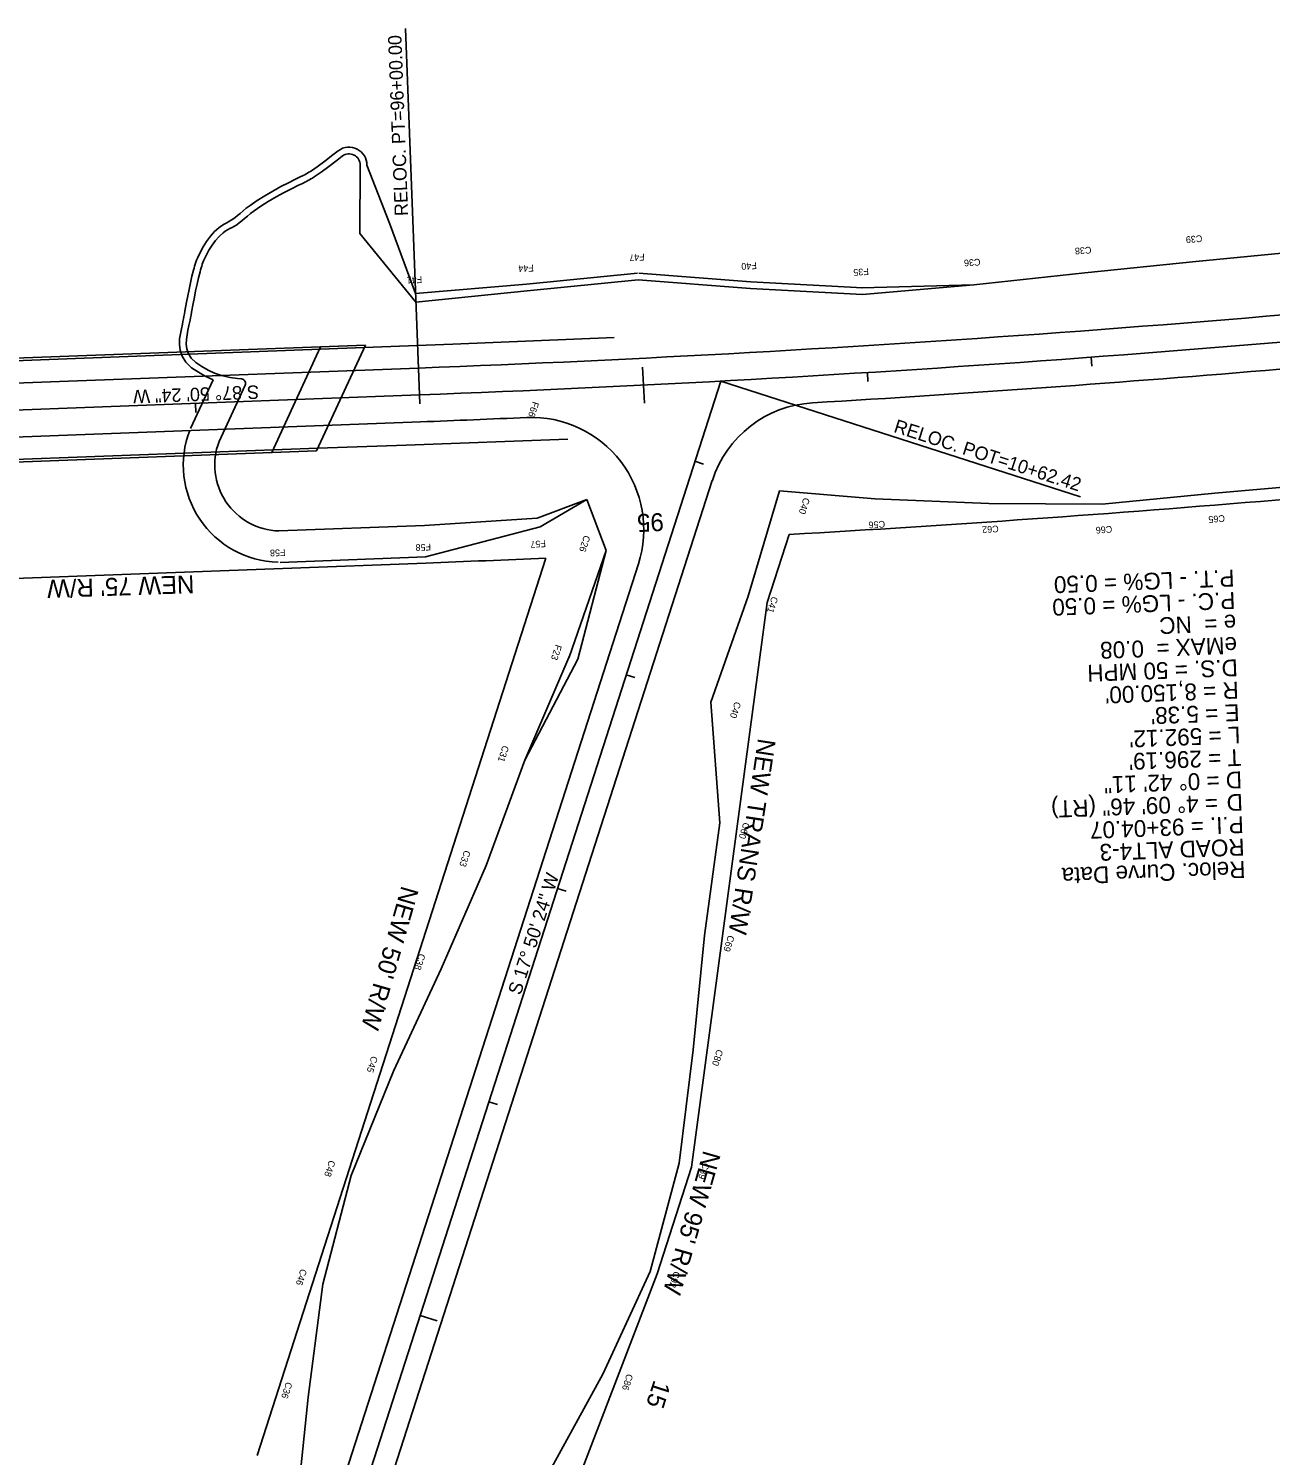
# Model space of a CAD drawing. Extents: x 1475170 to 1480100, y 1103245 to 1119475.
# Drawn here: x 1477070 to 1477624, y 1110840 to 1111476 of the extents above; entities that cross this region are included whole.
import ezdxf

# ---------------------------------------------------------------- set-up
doc = ezdxf.new("R2010")
doc.units = 0
for name, color, linetype in [('RD_HC_CL_Rel', 7, 'Continuous'), ('RD_HC_Data_Rel', 7, 'Continuous'), ('RD_HC_Data_Tic_Rel', 7, 'Continuous'), ('RD_HC_TX_Rel_Sta50', 7, 'Continuous'), ('RD_PD_Bridge', 7, 'Continuous'), ('RD_PD_CstnLmt', 7, 'Continuous'), ('RD_PD_CstnLmt_TX', 7, 'Continuous'), ('RD_PD_DR_ErosCtrl', 7, 'Continuous'), ('RD_PD_Final_TrvlWay', 7, 'Continuous'), ('RD_PD_GR', 7, 'Continuous'), ('RD_PD_RW', 7, 'Continuous'), ('RD_PD_RW_TX', 7, 'Continuous')]:
    doc.layers.add(name, color=color, linetype=linetype)

msp = doc.modelspace()

# ---------------------------------------------------------------- linework, layer by layer
at = {"layer": 'RD_HC_CL_Rel'}
for p, q in [((1477378.79, 1111318.79), (1477219.71, 1110824.5)), ((1477244.45, 1111312.61), (1477044.6, 1111305.07))]:
    msp.add_line(p, q, dxfattribs=at)
msp.add_arc((1476937.28, 1119456.82), 8150, 272.160003, 276.322689, dxfattribs=at)
at = {"layer": 'RD_HC_Data_Rel'}
for p, q in [((1477244.45, 1111312.61), (1477238.29, 1111475.96)), ((1477378.79, 1111318.79), (1477539.19, 1111267.17))]:
    msp.add_line(p, q, dxfattribs=at)
at = {"layer": 'RD_HC_Data_Tic_Rel'}
for p, q in [((1477344.36, 1111316.99), (1477343.96, 1111324.98)), ((1477543.97, 1111329.43), (1477544.26, 1111325.45)), ((1477444.2, 1111322.6), (1477444.45, 1111318.61)), ((1477244.45, 1111312.61), (1477244.61, 1111308.62)), ((1477344.36, 1111316.99), (1477344.76, 1111309)), ((1477144.53, 1111308.84), (1477144.68, 1111304.85)), ((1477367.28, 1111283.02), (1477371.09, 1111281.79)), ((1477336.64, 1111187.83), (1477340.45, 1111186.6)), ((1477306.01, 1111092.63), (1477309.82, 1111091.41)), ((1477275.37, 1110997.44), (1477279.18, 1110996.22)), ((1477244.74, 1110902.25), (1477252.35, 1110899.8))]:
    msp.add_line(p, q, dxfattribs=at)
at = {"layer": 'RD_PD_Bridge'}
for p, q in [((1477219.85, 1111333.7), (1476890.09, 1111321.26)), ((1477220.38, 1111334.85), (1476890.62, 1111322.41)), ((1477200.4, 1111334.09), (1477178.59, 1111286.99)), ((1477220.38, 1111334.85), (1477198.58, 1111287.74)), ((1477198.58, 1111287.74), (1476868.81, 1111275.3)), ((1477199.11, 1111288.89), (1476869.34, 1111276.45))]:
    msp.add_line(p, q, dxfattribs=at)
at = {"layer": 'RD_PD_CstnLmt'}
for p, q in [((1477640.21, 1111376.88), (1477590.68, 1111372.12)), ((1477590.68, 1111372.12), (1477541.16, 1111367)), ((1477342.01, 1111363.93), (1477292.47, 1111359.03)), ((1477392.02, 1111360.07), (1477342.01, 1111363.93)), ((1477541.16, 1111367), (1477491.64, 1111361.67)), ((1477292.47, 1111359.03), (1477242.9, 1111353.9)), ((1477442.03, 1111357.44), (1477392.02, 1111360.07)), ((1477491.64, 1111361.67), (1477442.03, 1111357.44)), ((1477166.74, 1111316.98), (1477155.09, 1111291.82)), ((1477649.24, 1111273.17), (1477599.03, 1111268.8)), ((1477404.96, 1111269.81), (1477391.02, 1111222.85)), ((1477447.71, 1111266.3), (1477404.96, 1111269.81)), ((1477599.03, 1111268.8), (1477548.85, 1111263.98)), ((1477319.02, 1111265.94), (1477296.91, 1111257.62)), ((1477319.02, 1111265.94), (1477327.67, 1111243.24)), ((1477498.32, 1111264.19), (1477447.71, 1111266.3)), ((1477548.85, 1111263.98), (1477498.32, 1111264.19)), ((1477246.65, 1111254.44), (1477181.76, 1111252)), ((1477296.91, 1111257.62), (1477246.65, 1111254.44)), ((1477327.67, 1111243.24), (1477315.07, 1111194.77)), ((1477391.02, 1111222.85), (1477374.42, 1111175.67)), ((1477315.07, 1111194.77), (1477291.5, 1111149.83)), ((1477374.42, 1111175.67), (1477378.37, 1111121.87)), ((1477291.5, 1111149.83), (1477274.27, 1111102.85)), ((1477378.37, 1111121.87), (1477371.5, 1111071.56)), ((1477274.27, 1111102.85), (1477254.14, 1111056.8)), ((1477371.5, 1111071.56), (1477366.44, 1111020.66)), ((1477254.14, 1111056.8), (1477232.95, 1111011.1)), ((1477366.44, 1111020.66), (1477360.31, 1110970.11)), ((1477232.95, 1111011.1), (1477214.04, 1110964.65)), ((1477360.31, 1110970.11), (1477347.31, 1110921.76)), ((1477214.04, 1110964.65), (1477201.34, 1110916.22)), ((1477347.31, 1110921.76), (1477326.29, 1110876)), ((1477201.34, 1110916.22), (1477194.83, 1110865.79)), ((1477326.29, 1110876), (1477301.75, 1110831.37)), ((1477194.83, 1110865.79), (1477189.48, 1110813.96))]:
    msp.add_line(p, q, dxfattribs=at)
for points in [[(1477210.05, 1111419.09), (1477207.71, 1111417.32), (1477204.03, 1111414.51), (1477200.58, 1111411.91), (1477197.49, 1111409.78), (1477196.76, 1111409.32), (1477196.06, 1111408.9), (1477195.37, 1111408.51), (1477194.7, 1111408.15), (1477194.03, 1111407.8), (1477193.36, 1111407.46), (1477192.91, 1111407.24), (1477191.96, 1111406.78), (1477190.45, 1111406.06), (1477187.45, 1111404.57), (1477184.09, 1111402.83), (1477180.55, 1111400.91), (1477177.02, 1111398.87), (1477173.68, 1111396.78), (1477170.69, 1111394.72), (1477169.13, 1111393.52), (1477167.74, 1111392.36), (1477166.46, 1111391.27), (1477165.26, 1111390.25), (1477164.1, 1111389.32), (1477162.96, 1111388.5), (1477161.97, 1111387.89), (1477160.97, 1111387.33), (1477159.95, 1111386.79), (1477158.93, 1111386.21), (1477157.89, 1111385.56), (1477156.86, 1111384.81), (1477155.18, 1111383.29), (1477153.54, 1111381.46), (1477151.99, 1111379.38), (1477150.56, 1111377.14), (1477149.3, 1111374.81), (1477148.23, 1111372.47), (1477147.91, 1111371.65), (1477147.62, 1111370.84), (1477147.35, 1111370.03), (1477147.09, 1111369.21), (1477146.84, 1111368.37), (1477146.61, 1111367.51), (1477145.93, 1111364.83), (1477145.28, 1111361.99), (1477144.67, 1111359.09), (1477144.1, 1111356.19), (1477143.57, 1111353.37), (1477142.85, 1111349.45), (1477142.63, 1111348.24), (1477142.41, 1111347.06), (1477142.18, 1111345.89), (1477141.94, 1111344.73), (1477141.69, 1111343.55), (1477141.24, 1111341.51), (1477140.82, 1111339.42), (1477140.52, 1111337.32), (1477140.45, 1111335.23), (1477140.68, 1111333.2), (1477141.32, 1111331.26), (1477142.72, 1111329.04), (1477144.74, 1111327.01), (1477147.44, 1111325.3), (1477150.26, 1111323.7), (1477153.09, 1111322.34), (1477156.21, 1111321.32), (1477156.84, 1111321.15), (1477157.47, 1111320.99), (1477158.11, 1111320.84), (1477158.74, 1111320.7), (1477159.38, 1111320.57), (1477160.02, 1111320.45), (1477163.37, 1111319.97), (1477165.1, 1111319.81)], [(1477242.9, 1111353.9), (1477217.88, 1111384.57), (1477218.06, 1111415.06)]]:
    msp.add_lwpolyline(points, dxfattribs=at)
for centre, radius, start, end in [((1477213.06, 1111415.09), 5, 359.65237, 126.96903), ((1477164.92, 1111317.82), 2, 335.15126, 84.8575), ((1477182.55, 1111281.37), 29.38, 159.16128, 268.47042)]:
    msp.add_arc(centre, radius, start, end, dxfattribs=at)
at = {"layer": 'RD_PD_DR_ErosCtrl'}
for p, q in [((1477292.16, 1111362.02), (1477242.75, 1111357.9)), ((1477341.71, 1111366.92), (1477292.17, 1111362.02)), ((1477392.25, 1111363.06), (1477342.24, 1111366.93)), ((1477442.19, 1111360.43), (1477392.17, 1111363.07)), ((1477491.64, 1111361.67), (1477441.77, 1111360.43)), ((1477152.43, 1111319.33), (1477142.41, 1111297.69)), ((1477319.02, 1111265.94), (1477298.32, 1111253.87)), ((1477298.32, 1111253.87), (1477247.18, 1111240.42)), ((1477327.67, 1111243.24), (1477311.2, 1111195.78)), ((1477247.18, 1111240.42), (1477182.29, 1111237.97)), ((1477311.52, 1111196.63), (1477291.5, 1111149.83))]:
    msp.add_line(p, q, dxfattribs=at)
for points in [[(1477208.25, 1111421.49), (1477205.89, 1111419.71), (1477202.22, 1111416.9), (1477198.82, 1111414.35), (1477195.84, 1111412.28), (1477195.19, 1111411.88), (1477194.55, 1111411.49), (1477193.92, 1111411.13), (1477193.3, 1111410.8), (1477192.67, 1111410.47), (1477192.03, 1111410.15), (1477191.59, 1111409.94), (1477190.66, 1111409.49), (1477189.14, 1111408.75), (1477186.09, 1111407.24), (1477182.68, 1111405.48), (1477179.09, 1111403.52), (1477175.48, 1111401.44), (1477172.03, 1111399.29), (1477168.92, 1111397.14), (1477167.26, 1111395.86), (1477165.81, 1111394.66), (1477164.51, 1111393.55), (1477163.35, 1111392.56), (1477162.29, 1111391.71), (1477161.3, 1111391), (1477160.45, 1111390.48), (1477159.53, 1111389.97), (1477158.5, 1111389.41), (1477157.39, 1111388.79), (1477156.22, 1111388.05), (1477154.97, 1111387.15), (1477153.05, 1111385.41), (1477151.22, 1111383.36), (1477149.52, 1111381.09), (1477147.98, 1111378.67), (1477146.61, 1111376.15), (1477145.47, 1111373.64), (1477145.11, 1111372.71), (1477144.79, 1111371.83), (1477144.49, 1111370.95), (1477144.22, 1111370.07), (1477143.96, 1111369.19), (1477143.71, 1111368.28), (1477143.01, 1111365.53), (1477142.35, 1111362.63), (1477141.73, 1111359.69), (1477141.16, 1111356.75), (1477140.62, 1111353.91), (1477139.9, 1111349.99), (1477139.68, 1111348.79), (1477139.46, 1111347.62), (1477139.24, 1111346.48), (1477139.01, 1111345.34), (1477138.76, 1111344.19), (1477138.3, 1111342.13), (1477137.86, 1111339.92), (1477137.53, 1111337.58), (1477137.44, 1111335.12), (1477137.74, 1111332.56), (1477138.58, 1111329.97), (1477140.36, 1111327.15), (1477142.85, 1111324.66), (1477145.9, 1111322.72), (1477148.87, 1111321.04), (1477152.43, 1111319.33)], [(1477242.75, 1111357.9), (1477231.08, 1111389.23), (1477221.06, 1111415.05)]]:
    msp.add_lwpolyline(points, dxfattribs=at)
for centre, radius, start, end in [((1477213.06, 1111415.09), 8, 359.65237, 126.96903), ((1477182.55, 1111281.37), 43.39, 159.16128, 268.47042)]:
    msp.add_arc(centre, radius, start, end, dxfattribs=at)
at = {"layer": 'RD_PD_Final_TrvlWay'}
for p, q in [((1477244, 1111324.6), (1476777.04, 1111306.99)), ((1477244.91, 1111300.62), (1476777.94, 1111283.01)), ((1477375.04, 1111274.5), (1477229.23, 1110821.43)), ((1477342.05, 1111237.28), (1477210.19, 1110827.56))]:
    msp.add_line(p, q, dxfattribs=at)
for centre, radius, start, end in [((1476937.28, 1119456.82), 8138, 272.160003, 276.322689), ((1476937.28, 1119456.82), 8162, 273.388369, 276.322689), ((1477422.64, 1111259.18), 50, 93.38837, 162.16), ((1476937.28, 1119456.82), 8162, 272.160003, 272.492854), ((1477294.46, 1111252.59), 50, 342.16, 92.49285)]:
    msp.add_arc(centre, radius, start, end, dxfattribs=at)
at = {"layer": 'RD_PD_GR'}
for p, q in [((1477259.32, 1111335.19), (1477331.26, 1111338.19)), ((1477219.85, 1111333.7), (1477259.32, 1111335.19)), ((1477310.54, 1111292.84), (1477238.58, 1111290.29)), ((1477238.58, 1111290.29), (1477199.11, 1111288.89))]:
    msp.add_line(p, q, dxfattribs=at)
at = {"layer": 'RD_PD_RW'}
for p, q in [((1477409.3, 1111250.39), (1477399.56, 1111220.1)), ((1477247.28, 1111237.67), (1477047.42, 1111230.13)), ((1477300.87, 1111239.86), (1477172.12, 1110839.82)), ((1477365.8, 1110968.34), (1477399.56, 1111220.1)), ((1477365.8, 1110968.34), (1477350.49, 1110920.74)), ((1477231.06, 1110610.9), (1477350.49, 1110920.74))]:
    msp.add_line(p, q, dxfattribs=at)
for radius, start, end in [(8220, 273.291963, 276.322689), (8225, 272.160003, 272.533591)]:
    msp.add_arc((1476937.28, 1119456.82), radius, start, end, dxfattribs=at)

# ---------------------------------------------------------------- texts
at = {"layer": 'RD_HC_Data_Rel'}
for s, height, rotation, p in [('RELOC. PT=96+00.00', 6, 92.16, (1477239.44, 1111392.48)), ('S 87%%d 50\' 24" W', 6, 182.16, (1477172.83, 1111316.92)), ('RELOC. POT=10+62.42', 6, 342.16, (1477455.56, 1111296.18)), ('P.T. - LG% = 0.50', 7.5, 182.16, (1477607.7, 1111234.74)), ('P.C. - LG% = 0.50', 7.5, 182.16, (1477608.08, 1111224.75)), ('e =  NC', 7.5, 182.16, (1477608.46, 1111214.75)), ('eMAX =  0.08', 7.5, 182.16, (1477608.83, 1111204.76)), ('D.S. = 50 MPH', 7.5, 182.16, (1477609.21, 1111194.77)), ("R = 8,150.00'", 7.5, 182.16, (1477609.59, 1111184.77)), ("E = 5.38'", 7.5, 182.16, (1477609.96, 1111174.78)), ("L = 592.12'", 7.5, 182.16, (1477610.34, 1111164.79)), ("T = 296.19'", 7.5, 182.16, (1477610.72, 1111154.8)), ('D = 0%%d 42\' 11"', 7.5, 182.16, (1477611.09, 1111144.8)), ('    = 4%%d 09\' 46" (RT)', 7.5, 182.16, (1477611.47, 1111134.81)), ('D', 7.5, 182.16, (1477611.47, 1111134.81)), ('P.I. = 93+04.07', 7.5, 182.16, (1477611.85, 1111124.82)), ('ROAD ALT4-3', 7.5, 182.16, (1477612.22, 1111114.82)), ('Reloc. Curve Data', 7.5, 182.16, (1477612.6, 1111104.83)), ('S 17%%d 50\' 24" W', 6, 72.16, (1477289.54, 1111044.74))]:
    msp.add_text(s, height=height, rotation=rotation, dxfattribs=at).set_placement(p)
at = {"layer": 'RD_HC_TX_Rel_Sta50'}
for s, rotation, p in [('95', 182.86302, (1477353.19, 1111260.02)), ('15', 252.16, (1477349.04, 1110873.81))]:
    msp.add_text(s, height=8, rotation=rotation, dxfattribs=at).set_placement(p)
at = {"layer": 'RD_PD_CstnLmt_TX'}
for s, rotation, p in [('C39', 184.62056, (1477593.39, 1111383.87)), ('F47', 182.86302, (1477344.83, 1111375.59)), ('C38', 184.26905, (1477543.95, 1111378.74)), ('F44', 182.51151, (1477295.38, 1111370.67)), ('F40', 183.21453, (1477394.79, 1111371.75)), ('F35', 183.56604, (1477444.73, 1111369.13)), ('C36', 183.91754, (1477494.5, 1111373.39)), ('F41', 182.16, (1477245.6, 1111365.51)), ('F66', 252.16, (1477294.97, 1111309.89)), ('C40', 252.16, (1477415.77, 1111267.05)), ('C56', 183.56604, (1477451.97, 1111256.55)), ('C62', 183.91754, (1477502.61, 1111254.46)), ('C66', 184.26905, (1477553.24, 1111254.28)), ('C65', 184.62056, (1477603.47, 1111259.12)), ('F57', 182.51151, (1477300.75, 1111247.78)), ('C26', 252.16, (1477317.84, 1111250.24)), ('F58', 182.16, (1477184.66, 1111243.86)), ('F58', 182.16, (1477249.54, 1111246.31)), ('C41', 252.16, (1477401.57, 1111222.99)), ('F23', 252.16, (1477305.17, 1111201.55)), ('C40', 252.16, (1477385.06, 1111176.08)), ('C31', 252.16, (1477281.58, 1111156.56)), ('C60', 252.16, (1477389.01, 1111122.28)), ('C33', 252.16, (1477264.44, 1111109.85)), ('C69', 252.16, (1477382.14, 1111071.97)), ('C38', 252.16, (1477244.31, 1111063.8)), ('C80', 252.16, (1477377.08, 1111021.07)), ('C45', 252.16, (1477223.12, 1111018.1)), ('C48', 252.16, (1477204.21, 1110971.65)), ('C89', 252.16, (1477370.95, 1110970.52)), ('C46', 252.16, (1477191.51, 1110923.22)), ('C92', 252.16, (1477357.94, 1110922.15)), ('C36', 252.16, (1477185.01, 1110872.78)), ('C86', 252.16, (1477336.93, 1110876.41))]:
    msp.add_text(s, height=3, rotation=rotation, dxfattribs=at).set_placement(p)
at = {"layer": 'RD_PD_RW_TX'}
for s, rotation, p in [("NEW 75' R/W", 181.87912, (1477143.92, 1111232.26)), ('NEW TRANS R/W', 261.36556, (1477395.44, 1111159.78)), ("NEW 50' R/W", 253.93886, (1477236.54, 1111094.14)), ("NEW 95' R/W", 253.93886, (1477371.17, 1110976.15))]:
    msp.add_text(s, height=8, rotation=rotation, dxfattribs=at).set_placement(p)

doc.saveas('drawing.dxf')
